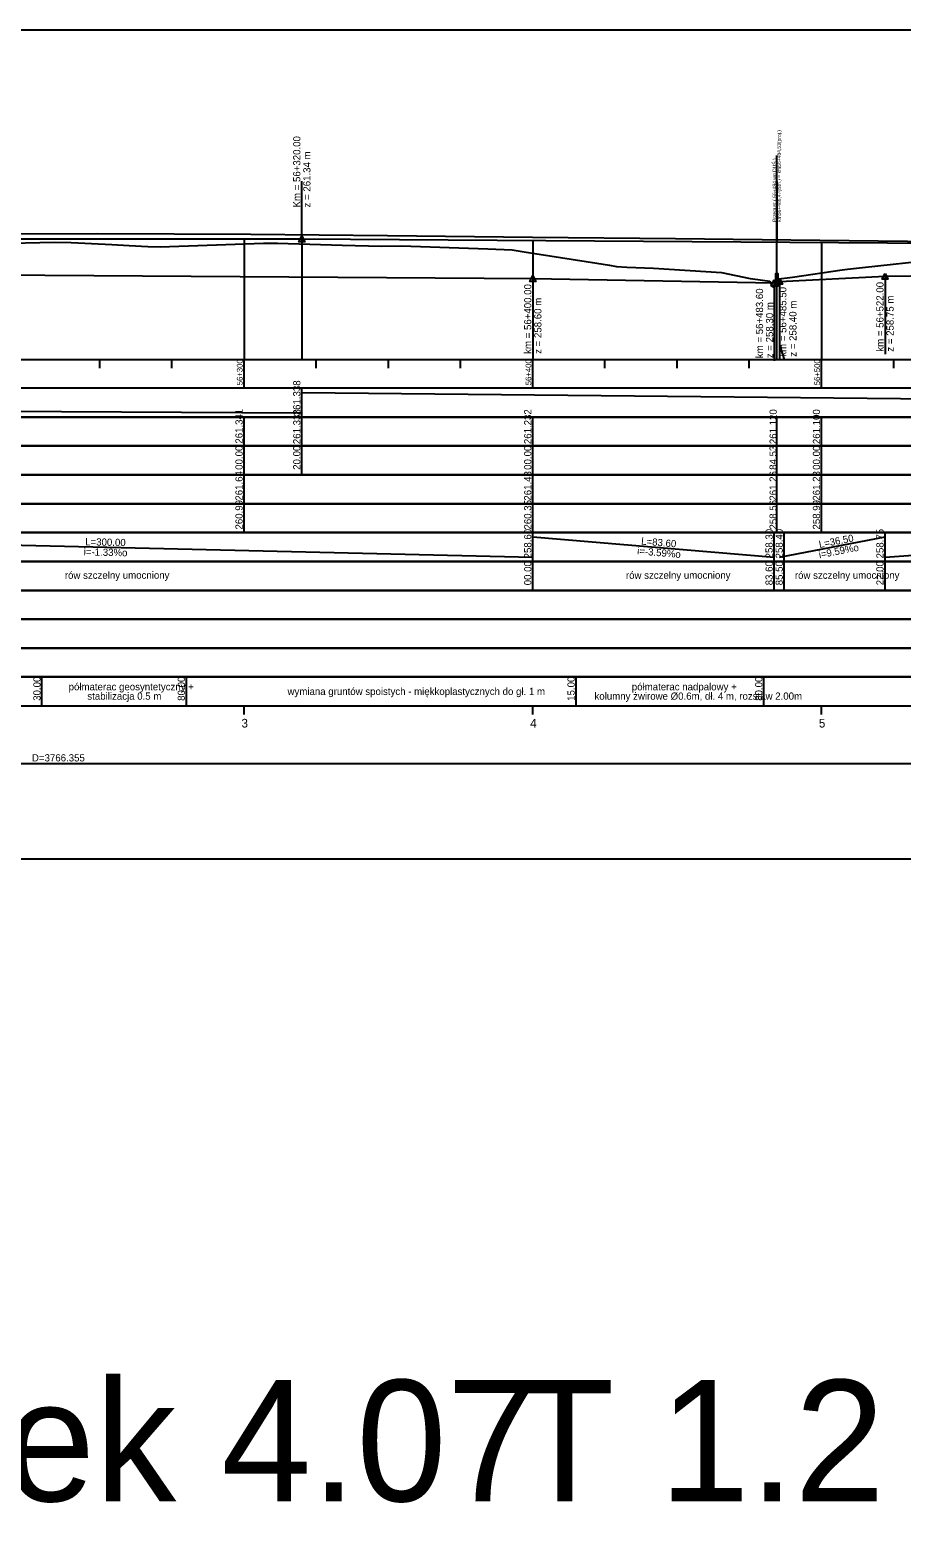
# Model space of a CAD drawing. Extents: x 6445630 to 6518227, y 5499240 to 5511716.
# Drawn here: x 6455457 to 6455759, y 5508183 to 5508705 of the extents above; entities that cross this region are included whole.
import ezdxf

# ---------------------------------------------------------------- set-up
doc = ezdxf.new("R2010")
doc.units = 0
for name, color, linetype in [('TOR_PROF-obiekty+opisy', 7, 'Continuous'), ('TOR_PROF-opisy pomocnicze', 7, 'Continuous'), ('TOR_PROF-rowy otwarte', 7, 'Continuous'), ('TOR_PROF-tabelka-geometria T1', 7, 'Continuous'), ('TOR_PROF-tabelka-kilometracja', 7, 'Continuous'), ('TOR_PROF-tabelka-odleglosci T1', 7, 'Continuous'), ('TOR_PROF-tabelka-pochylenia proj T1', 7, 'Continuous'), ('TOR_PROF-tabelka-rodzaj rowu T1', 7, 'Continuous'), ('TOR_PROF-tabelka-rowyT1', 7, 'Continuous'), ('TOR_PROF-tabelka-rurociagi T1', 7, 'Continuous'), ('TOR_PROF-tabelka-rzedne istn T1', 7, 'Continuous'), ('TOR_PROF-tabelka-rzedne proj T1', 7, 'Continuous'), ('TOR_PROF-tabelka-teren istniejacy T1', 7, 'Continuous'), ('TOR_PROF-tabelka-warstwa ochronna T1', 7, 'Continuous'), ('TOR_PROF-tor istniejacy T2', 7, 'Continuous'), ('TOR_PROF-tor projektowany', 7, 'Continuous'), ('TOR_PROF-uklad odniesienia', 7, 'Continuous'), ('TOR_PROF-warstwa ochronna', 7, 'Continuous'), ('TOR_RAMKI-dodatkowe3', 7, 'Continuous'), ('TOR_RAMKI-MASKA WYCIECIA', 7, 'Continuous')]:
    doc.layers.add(name, color=color, linetype=linetype)

msp = doc.modelspace()

# ---------------------------------------------------------------- linework, layer by layer
at = {"layer": 'TOR_PROF-obiekty+opisy'}
for p, q in [((6455715.74, 5508591.29), (6455715.74, 5508661.89)), ((6455715.74, 5508652.89), (6455715.74, 5508631.89))]:
    msp.add_line(p, q, dxfattribs=at)
for points in [[(6455716.2, 5508620.87), (6455715.28, 5508620.87), (6455715.28, 5508616.79), (6455716.2, 5508616.79)], [(6455716.12, 5508620.33), (6455715.37, 5508620.33), (6455715.37, 5508617.33), (6455716.12, 5508617.33)]]:
    msp.add_lwpolyline(points, close=True, dxfattribs=at)
for points in [[(6455716.2, 5508616.79), (6455716.2, 5508620.87), (6455715.28, 5508620.87), (6455715.28, 5508616.79), (6455716.2, 5508616.79)], [(6455716.12, 5508617.33), (6455715.37, 5508617.33), (6455715.37, 5508620.33), (6455716.12, 5508620.33), (6455716.12, 5508617.33)]]:
    msp.add_lwpolyline(points, dxfattribs=at)
at = {"layer": 'TOR_PROF-opisy pomocnicze'}
for p, q in [((6455551.21, 5508632.98), (6455551.21, 5508652.98)), ((6455551.21, 5508632.98), (6455551.21, 5508652.98)), ((6455631.21, 5508619.29), (6455631.21, 5508592.29)), ((6455714.81, 5508617.79), (6455714.81, 5508590.79)), ((6455716.71, 5508618.29), (6455716.71, 5508591.29)), ((6455753.21, 5508620.04), (6455753.21, 5508593.04))]:
    msp.add_line(p, q, dxfattribs=at)
for points in [[(6455551.21, 5508633.98), (6455552.21, 5508631.98), (6455550.21, 5508631.98)], [(6455551.21, 5508633.98), (6455552.21, 5508631.98), (6455550.21, 5508631.98)], [(6455631.21, 5508620.29), (6455632.21, 5508618.29), (6455630.21, 5508618.29)], [(6455714.81, 5508618.79), (6455715.81, 5508616.79), (6455713.81, 5508616.79)], [(6455716.71, 5508619.29), (6455717.71, 5508617.29), (6455715.71, 5508617.29)], [(6455753.21, 5508621.04), (6455754.21, 5508619.04), (6455752.21, 5508619.04)]]:
    msp.add_lwpolyline(points, close=True, dxfattribs=at)
at = {"layer": 'TOR_PROF-rowy otwarte'}
for p, q in [((6455331.21, 5508621.29), (6455631.21, 5508619.29)), ((6455631.21, 5508619.29), (6455714.81, 5508617.79)), ((6455716.71, 5508618.29), (6455753.21, 5508620.04)), ((6455753.21, 5508620.04), (6455851.21, 5508621.79))]:
    msp.add_line(p, q, dxfattribs=at)
msp.add_lwpolyline([(6455716.71, 5508618.29), (6455716.71, 5508596.29), (6455718.31, 5508591.29), (6455718.31, 5508591.29)], dxfattribs=at)
at = {"layer": 'TOR_PROF-tabelka-geometria T1'}
for points in [[(6452331.21, 5508451.29), (6453331.21, 5508451.29), (6453331.21, 5508448.62), (6453416.22, 5508448.62), (6453416.22, 5508451.29), (6453496.22, 5508451.29), (6453496.22, 5508453.96), (6453581.21, 5508453.96), (6453581.21, 5508451.29), (6457347.56, 5508451.29), (6457347.56, 5508448.62), (6457429.11, 5508448.62), (6457429.11, 5508451.29), (6457509.11, 5508451.29), (6457509.11, 5508453.96), (6457590.67, 5508453.96), (6457590.67, 5508451.29), (6459780.93, 5508451.29)], [(6452331.21, 5508451.29), (6462731.21, 5508451.29)]]:
    msp.add_lwpolyline(points, dxfattribs=at)
at = {"layer": 'TOR_PROF-tabelka-kilometracja'}
for points in [[(6455531.21, 5508468.29), (6455531.21, 5508471.29)], [(6455631.21, 5508468.29), (6455631.21, 5508471.29)], [(6455731.21, 5508468.29), (6455731.21, 5508471.29)]]:
    msp.add_lwpolyline(points, dxfattribs=at)
at = {"layer": 'TOR_PROF-tabelka-odleglosci T1'}
msp.add_lwpolyline([(6452331.21, 5508551.29), (6462731.21, 5508551.29), (6462731.21, 5508561.29), (6452331.21, 5508561.29)], close=True, dxfattribs=at)
for points in [[(6455531.21, 5508551.29), (6455531.21, 5508561.29)], [(6455551.21, 5508551.29), (6455551.21, 5508561.29)], [(6455631.21, 5508551.29), (6455631.21, 5508561.29)], [(6455715.74, 5508551.29), (6455715.74, 5508561.29)], [(6455731.21, 5508551.29), (6455731.21, 5508561.29)]]:
    msp.add_lwpolyline(points, dxfattribs=at)
at = {"layer": 'TOR_PROF-tabelka-pochylenia proj T1'}
msp.add_lwpolyline([(6452331.21, 5508571.29), (6462731.21, 5508571.29), (6462731.21, 5508581.29), (6452331.21, 5508581.29)], close=True, dxfattribs=at)
for points in [[(6455551.21, 5508571.29), (6455551.21, 5508581.29)], [(6454281.21, 5508579.79), (6455551.21, 5508572.79)], [(6455551.21, 5508579.79), (6456253.75, 5508572.79)]]:
    msp.add_lwpolyline(points, dxfattribs=at)
at = {"layer": 'TOR_PROF-tabelka-rodzaj rowu T1'}
for points in [[(6452331.21, 5508511.29), (6462731.21, 5508511.29), (6462731.21, 5508521.29), (6452331.21, 5508521.29)], [(6452331.21, 5508511.29), (6462731.21, 5508511.29), (6462731.21, 5508521.29), (6452331.21, 5508521.29)], [(6452331.21, 5508491.29), (6462731.21, 5508491.29), (6462731.21, 5508501.29), (6452331.21, 5508501.29)]]:
    msp.add_lwpolyline(points, close=True, dxfattribs=at)
for points in [[(6455631.21, 5508511.29), (6455631.21, 5508521.29)], [(6455714.81, 5508511.29), (6455714.81, 5508521.29)], [(6455718.31, 5508511.29), (6455718.31, 5508521.29)], [(6455753.21, 5508511.29), (6455753.21, 5508521.29)]]:
    msp.add_lwpolyline(points, dxfattribs=at)
at = {"layer": 'TOR_PROF-tabelka-rowyT1'}
msp.add_lwpolyline([(6452331.21, 5508521.29), (6462731.21, 5508521.29), (6462731.21, 5508531.29), (6452331.21, 5508531.29)], close=True, dxfattribs=at)
msp.add_lwpolyline([(6452331.21, 5508521.29), (6462731.21, 5508521.29), (6462731.21, 5508531.29), (6452331.21, 5508531.29)], close=True, dxfattribs=at)
msp.add_lwpolyline([(6452331.21, 5508521.29), (6462731.21, 5508521.29), (6462731.21, 5508531.29), (6452331.21, 5508531.29)], close=True, dxfattribs=at)
for points in [[(6455331.21, 5508529.79), (6455631.21, 5508522.79)], [(6455631.21, 5508521.29), (6455631.21, 5508531.29)], [(6455631.21, 5508529.79), (6455714.81, 5508522.79)], [(6455714.81, 5508521.29), (6455714.81, 5508531.29)], [(6455716.71, 5508522.79), (6455753.21, 5508529.79)], [(6455718.31, 5508521.29), (6455718.31, 5508531.29)], [(6455753.21, 5508521.29), (6455753.21, 5508531.29)], [(6455753.21, 5508522.79), (6455851.21, 5508529.79)]]:
    msp.add_lwpolyline(points, dxfattribs=at)
at = {"layer": 'TOR_PROF-tabelka-rurociagi T1'}
msp.add_lwpolyline([(6452331.21, 5508501.29), (6462731.21, 5508501.29), (6462731.21, 5508511.29), (6452331.21, 5508511.29)], close=True, dxfattribs=at)
at = {"layer": 'TOR_PROF-tabelka-rzedne istn T1'}
msp.add_lwpolyline([(6452331.21, 5508541.29), (6462731.21, 5508541.29), (6462731.21, 5508551.29), (6452331.21, 5508551.29)], close=True, dxfattribs=at)
for points in [[(6455531.21, 5508541.29), (6455531.21, 5508551.29)], [(6455631.21, 5508541.29), (6455631.21, 5508551.29)], [(6455715.74, 5508541.29), (6455715.74, 5508551.29)], [(6455731.21, 5508541.29), (6455731.21, 5508551.29)], [(6455531.21, 5508531.29), (6455531.21, 5508541.29)], [(6455531.21, 5508531.29), (6455531.21, 5508541.29)], [(6455531.21, 5508531.29), (6455531.21, 5508541.29)], [(6455531.21, 5508531.29), (6455531.21, 5508541.29)], [(6455631.21, 5508531.29), (6455631.21, 5508541.29)], [(6455631.21, 5508531.29), (6455631.21, 5508541.29)], [(6455631.21, 5508531.29), (6455631.21, 5508541.29)], [(6455631.21, 5508531.29), (6455631.21, 5508541.29)], [(6455715.74, 5508531.29), (6455715.74, 5508541.29)], [(6455731.21, 5508531.29), (6455731.21, 5508541.29)], [(6455731.21, 5508531.29), (6455731.21, 5508541.29)], [(6455731.21, 5508531.29), (6455731.21, 5508541.29)], [(6455731.21, 5508531.29), (6455731.21, 5508541.29)]]:
    msp.add_lwpolyline(points, dxfattribs=at)
at = {"layer": 'TOR_PROF-tabelka-rzedne proj T1'}
msp.add_lwpolyline([(6452331.21, 5508561.29), (6462731.21, 5508561.29), (6462731.21, 5508571.29), (6452331.21, 5508571.29)], close=True, dxfattribs=at)
for points in [[(6455531.21, 5508561.29), (6455531.21, 5508571.29)], [(6455551.21, 5508561.29), (6455551.21, 5508571.29)], [(6455631.21, 5508561.29), (6455631.21, 5508571.29)], [(6455715.74, 5508561.29), (6455715.74, 5508571.29)], [(6455731.21, 5508561.29), (6455731.21, 5508571.29)]]:
    msp.add_lwpolyline(points, dxfattribs=at)
at = {"layer": 'TOR_PROF-tabelka-teren istniejacy T1'}
msp.add_lwpolyline([(6452331.21, 5508531.29), (6462731.21, 5508531.29), (6462731.21, 5508541.29), (6452331.21, 5508541.29)], close=True, dxfattribs=at)
msp.add_lwpolyline([(6452331.21, 5508531.29), (6462731.21, 5508531.29), (6462731.21, 5508541.29), (6452331.21, 5508541.29)], close=True, dxfattribs=at)
msp.add_lwpolyline([(6452331.21, 5508531.29), (6462731.21, 5508531.29), (6462731.21, 5508541.29), (6452331.21, 5508541.29)], close=True, dxfattribs=at)
msp.add_lwpolyline([(6452331.21, 5508531.29), (6462731.21, 5508531.29), (6462731.21, 5508541.29), (6452331.21, 5508541.29)], close=True, dxfattribs=at)
at = {"layer": 'TOR_PROF-tabelka-warstwa ochronna T1'}
msp.add_lwpolyline([(6452331.21, 5508481.29), (6462731.21, 5508481.29), (6462731.21, 5508491.29), (6452331.21, 5508491.29)], close=True, dxfattribs=at)
at = {"layer": 'TOR_PROF-tor istniejacy T2'}
msp.add_lwpolyline([(6455781.22, 5508631.84), (6455730.64, 5508632.44), (6455680.65, 5508632.99), (6455631.1, 5508633.44), (6455580.84, 5508634.09), (6455533.6, 5508634.49), (6455480.41, 5508634.74), (6455431.02, 5508634.69), (6455379.72, 5508634.69), (6455329.04, 5508634.69), (6455279.58, 5508634.74), (6455230.6, 5508634.64), (6455180.37, 5508634.54)], dxfattribs=at)
at = {"layer": 'TOR_PROF-tor projektowany'}
for p, q in [((6454281.21, 5508633.98), (6455551.21, 5508632.98)), ((6454281.21, 5508633.98), (6455551.21, 5508632.98)), ((6455551.21, 5508632.98), (6456180.45, 5508628.82)), ((6455551.21, 5508632.98), (6456253.75, 5508628.33))]:
    msp.add_line(p, q, dxfattribs=at)
for points in [[(6455531.21, 5508633), (6455531.21, 5508596.29), (6455531.21, 5508591.29), (6455531.21, 5508591.29)], [(6455531.21, 5508633), (6455531.21, 5508596.29), (6455531.21, 5508591.29), (6455531.21, 5508591.29)], [(6455551.21, 5508632.98), (6455551.21, 5508596.29), (6455551.21, 5508591.29), (6455551.21, 5508591.29)], [(6455551.21, 5508632.98), (6455551.21, 5508596.29), (6455551.21, 5508591.29), (6455551.21, 5508591.29)], [(6455551.21, 5508632.98), (6455551.21, 5508596.29), (6455551.21, 5508591.29), (6455551.21, 5508591.29)], [(6455551.21, 5508632.98), (6455551.21, 5508596.29), (6455551.21, 5508591.29), (6455551.21, 5508591.29)], [(6455631.21, 5508632.45), (6455631.21, 5508596.29), (6455631.21, 5508591.29), (6455631.21, 5508591.29)], [(6455631.21, 5508632.45), (6455631.21, 5508596.29), (6455631.21, 5508591.29), (6455631.21, 5508591.29)], [(6455731.21, 5508631.79), (6455731.21, 5508596.29), (6455731.21, 5508591.29), (6455731.21, 5508591.29)], [(6455731.21, 5508631.79), (6455731.21, 5508596.29), (6455731.21, 5508591.29), (6455731.21, 5508591.29)]]:
    msp.add_lwpolyline(points, dxfattribs=at)
at = {"layer": 'TOR_PROF-uklad odniesienia'}
for p, q in [((6452331.21, 5508591.29), (6462731.21, 5508591.29)), ((6452331.21, 5508591.29), (6462731.21, 5508591.29)), ((6455481.21, 5508588.29), (6455481.21, 5508591.29)), ((6455481.21, 5508588.29), (6455481.21, 5508591.29)), ((6455506.21, 5508588.29), (6455506.21, 5508591.29)), ((6455506.21, 5508588.29), (6455506.21, 5508591.29)), ((6455531.21, 5508581.29), (6455531.21, 5508591.29)), ((6455531.21, 5508581.29), (6455531.21, 5508591.29)), ((6455556.21, 5508588.29), (6455556.21, 5508591.29)), ((6455556.21, 5508588.29), (6455556.21, 5508591.29)), ((6455581.21, 5508588.29), (6455581.21, 5508591.29)), ((6455581.21, 5508588.29), (6455581.21, 5508591.29)), ((6455606.21, 5508588.29), (6455606.21, 5508591.29)), ((6455606.21, 5508588.29), (6455606.21, 5508591.29)), ((6455631.21, 5508581.29), (6455631.21, 5508591.29)), ((6455631.21, 5508581.29), (6455631.21, 5508591.29)), ((6455656.21, 5508588.29), (6455656.21, 5508591.29)), ((6455656.21, 5508588.29), (6455656.21, 5508591.29)), ((6455681.21, 5508588.29), (6455681.21, 5508591.29)), ((6455681.21, 5508588.29), (6455681.21, 5508591.29)), ((6455706.21, 5508588.29), (6455706.21, 5508591.29)), ((6455706.21, 5508588.29), (6455706.21, 5508591.29)), ((6455731.21, 5508581.29), (6455731.21, 5508591.29)), ((6455731.21, 5508581.29), (6455731.21, 5508591.29)), ((6455756.21, 5508588.29), (6455756.21, 5508591.29)), ((6455756.21, 5508588.29), (6455756.21, 5508591.29))]:
    msp.add_line(p, q, dxfattribs=at)
at = {"layer": 'TOR_PROF-warstwa ochronna'}
msp.add_lwpolyline([(6452331.21, 5508471.29), (6462731.21, 5508471.29), (6462731.21, 5508481.29), (6452331.21, 5508481.29)], close=True, dxfattribs=at)
for points in [[(6455461.21, 5508471.29), (6455461.21, 5508481.29)], [(6455511.21, 5508471.29), (6455511.21, 5508481.29)], [(6455646.21, 5508471.29), (6455646.21, 5508481.29)], [(6455711.21, 5508471.29), (6455711.21, 5508481.29)]]:
    msp.add_lwpolyline(points, dxfattribs=at)
at = {"layer": 'TOR_RAMKI-dodatkowe3'}
for p, q in [((6455439.28, 5508631.3), (6455465.57, 5508631.92)), ((6455465.57, 5508631.92), (6455471.29, 5508631.8)), ((6455471.29, 5508631.8), (6455485.43, 5508631.04)), ((6455485.43, 5508631.04), (6455491.36, 5508630.74)), ((6455491.36, 5508630.74), (6455497.84, 5508630.4)), ((6455497.84, 5508630.4), (6455502.18, 5508630.24)), ((6455502.18, 5508630.24), (6455537.96, 5508631.47)), ((6455537.96, 5508631.47), (6455541.42, 5508631.48)), ((6455541.42, 5508631.48), (6455541.89, 5508631.48)), ((6455541.89, 5508631.48), (6455542.76, 5508631.48)), ((6455542.76, 5508631.48), (6455565.24, 5508630.84)), ((6455565.24, 5508630.84), (6455578.8, 5508630.54)), ((6455578.8, 5508630.54), (6455585.63, 5508630.63)), ((6455585.63, 5508630.63), (6455615.65, 5508629.52)), ((6455615.65, 5508629.52), (6455624.02, 5508629.19)), ((6455624.02, 5508629.19), (6455628.2, 5508628.49)), ((6455628.2, 5508628.49), (6455653.4, 5508624.56)), ((6455653.4, 5508624.56), (6455657.77, 5508623.86)), ((6455657.77, 5508623.86), (6455660.22, 5508623.44)), ((6455660.22, 5508623.44), (6455663.8, 5508623.25)), ((6455663.8, 5508623.25), (6455673.06, 5508622.86)), ((6455673.06, 5508622.86), (6455696.53, 5508621.42)), ((6455721.11, 5508619.79), (6455738.35, 5508622.29)), ((6455738.35, 5508622.29), (6455740.19, 5508622.55)), ((6455740.19, 5508622.55), (6455745.45, 5508623.12)), ((6455745.45, 5508623.12), (6455775.55, 5508626.44)), ((6455696.53, 5508621.42), (6455706.56, 5508619.34)), ((6455706.56, 5508619.34), (6455706.58, 5508619.33)), ((6455706.58, 5508619.33), (6455713.27, 5508618.34)), ((6455713.27, 5508618.34), (6455713.66, 5508617.47)), ((6455713.66, 5508617.47), (6455714.26, 5508616.4)), ((6455714.79, 5508616.49), (6455715.03, 5508617.9)), ((6455715.03, 5508617.9), (6455715.3, 5508619.01)), ((6455715.3, 5508619.01), (6455715.52, 5508619.07)), ((6455715.52, 5508619.07), (6455721.11, 5508619.79)), ((6455714.26, 5508616.4), (6455714.46, 5508616.44)), ((6455714.46, 5508616.44), (6455714.79, 5508616.49))]:
    msp.add_line(p, q, dxfattribs=at)
at = {"layer": 'TOR_RAMKI-MASKA WYCIECIA'}
msp.add_lwpolyline([(6454268.59, 5508418.29), (6456268.59, 5508418.29), (6456268.59, 5508705.29), (6454268.59, 5508705.29)], close=True, dxfattribs=at)

# ---------------------------------------------------------------- texts
at = {"layer": 'TOR_PROF-obiekty+opisy'}
for s, p in [(' km56+486,47(istn.) = km56+484,53(proj.) ', (6455717.13, 5508638.39)), (' Przepust ( 56+484 wg DUŚ )', (6455715.52, 5508638.39))]:
    msp.add_text(s, height=1.25, rotation=90, dxfattribs=at).set_placement(p)
at = {"layer": 'TOR_PROF-opisy pomocnicze'}
for s, p in [('Km = 56+320.00', (6455550.71, 5508643.88)), ('Km = 56+320.00', (6455550.71, 5508643.88)), ('z = 261.34 m', (6455554.21, 5508643.88)), ('z = 261.34 m', (6455554.21, 5508643.88)), ('km = 56+400.00', (6455630.71, 5508593.19)), ('km = 56+522.00', (6455752.71, 5508593.94)), ('z = 258.60 m', (6455634.21, 5508593.19)), ('km = 56+483.60', (6455710.98, 5508591.69)), ('km = 56+485.50', (6455719.06, 5508592.19)), ('z = 258.75 m', (6455756.21, 5508593.94)), ('z = 258.30 m', (6455714.48, 5508591.69)), ('z = 258.40 m', (6455722.56, 5508592.19))]:
    msp.add_text(s, height=2.5, rotation=90, dxfattribs=at).set_placement(p)
at = {"layer": 'TOR_PROF-tabelka-geometria T1'}
msp.add_text('D=3766.355', height=2.5, dxfattribs=at).set_placement((6455457.74, 5508452.04))
at = {"layer": 'TOR_PROF-tabelka-kilometracja'}
for s, p in [('3', (6455530.32, 5508463.79)), ('4', (6455630.32, 5508463.79)), ('5', (6455730.31, 5508463.79))]:
    msp.add_text(s, height=3, dxfattribs=at).set_placement(p)
at = {"layer": 'TOR_PROF-tabelka-odleglosci T1'}
for s, p in [('00.00', (6455530.71, 5508553.03)), ('20.00', (6455550.71, 5508553.03)), ('00.00', (6455630.71, 5508553.03)), ('84.53', (6455715.71, 5508553.03)), ('00.00', (6455730.71, 5508553.03))]:
    msp.add_text(s, height=2.5, rotation=90, dxfattribs=at).set_placement(p)
at = {"layer": 'TOR_PROF-tabelka-pochylenia proj T1'}
msp.add_text('261.338', height=2.5, rotation=90, dxfattribs=at).set_placement((6455550.71, 5508571.92))
at = {"layer": 'TOR_PROF-tabelka-rodzaj rowu T1'}
for s, p in [('00.00', (6455630.71, 5508513.04)), ('83.60', (6455714.31, 5508513.04)), ('85.50', (6455717.81, 5508513.04)), ('22.00', (6455752.71, 5508513.04))]:
    msp.add_text(s, height=2.5, rotation=90, dxfattribs=at).set_placement(p)
at = {"layer": 'TOR_PROF-tabelka-rowyT1'}
for s, rotation, p in [('L=300.00', 358.6633, (6455476.15, 5508526.91)), ('258.60', 90, (6455630.71, 5508522.36)), ('L=83.60', 355.2137, (6455668.67, 5508527.15)), ('258.30', 90, (6455714.31, 5508522.36)), ('258.40', 90, (6455717.81, 5508522.36)), ('L=36.50', 10.8564, (6455730.55, 5508525.95)), ('258.75', 90, (6455752.71, 5508522.35)), ('i=-1.33%o', 358.6633, (6455475.64, 5508523.42)), ('i=-3.59%o', 355.2137, (6455667.28, 5508523.76)), ('i=9.59%o', 10.8564, (6455730.52, 5508522.38)), ('rów szczelny umocniony', 0.087, (6455469.13, 5508515.27)), ('rów szczelny umocniony', 0.087, (6455663.47, 5508515.27)), ('rów szczelny umocniony', 0.087, (6455721.99, 5508515.27))]:
    msp.add_text(s, height=2.5, rotation=rotation, dxfattribs=at).set_placement(p)
at = {"layer": 'TOR_PROF-tabelka-rzedne istn T1'}
for s, p in [('261.64', (6455530.71, 5508542.36)), ('261.43', (6455630.71, 5508542.35)), ('261.26', (6455715.71, 5508542.35)), ('261.23', (6455730.71, 5508542.35)), ('260.99', (6455530.71, 5508532.36)), ('260.35', (6455630.71, 5508532.35)), ('258.56', (6455715.71, 5508532.35)), ('258.99', (6455730.71, 5508532.36))]:
    msp.add_text(s, height=2.5, rotation=90, dxfattribs=at).set_placement(p)
at = {"layer": 'TOR_PROF-tabelka-rzedne proj T1'}
for s, p in [('261.341', (6455530.71, 5508562.09)), ('261.338', (6455550.71, 5508561.92)), ('261.232', (6455630.71, 5508561.93)), ('261.120', (6455715.71, 5508561.93)), ('261.100', (6455730.71, 5508561.93))]:
    msp.add_text(s, height=2.5, rotation=90, dxfattribs=at).set_placement(p)
at = {"layer": 'TOR_PROF-uklad odniesienia'}
for s, p in [('56+300', (6455530.71, 5508582.31)), ('56+300', (6455530.71, 5508582.31)), ('56+400', (6455630.71, 5508582.31)), ('56+400', (6455630.71, 5508582.31)), ('56+500', (6455730.71, 5508582.31)), ('56+500', (6455730.71, 5508582.31))]:
    msp.add_text(s, height=2, rotation=90, dxfattribs=at).set_placement(p)
for s, p in [('Rysunek 4.07', (6455289.16, 5508195.84)), ('T 1.2', (6455625.16, 5508195.84))]:
    msp.add_text(s, height=42, dxfattribs=at).set_placement(p)
at = {"layer": 'TOR_PROF-warstwa ochronna'}
for s, rotation, p in [('30.00', 90, (6455460.71, 5508473.04)), ('80.00', 90, (6455510.71, 5508473.04)), ('15.00', 90, (6455645.71, 5508473.04)), ('80.00', 90, (6455710.71, 5508473.04)), ('półmaterac geosyntetyczny +', 360, (6455470.44, 5508476.66)), ('stabilizacja 0.5 m', 360, (6455476.92, 5508473.42)), ('wymiana gruntów spoistych - miękkoplastycznych do gł. 1 m', 360, (6455546.26, 5508475.04)), ('kolumny żwirowe Ø0.6m, dł. 4 m, rozstaw 2.00m', 360, (6455652.58, 5508473.42)), ('półmaterac nadpalowy +', 360, (6455665.51, 5508476.66))]:
    msp.add_text(s, height=2.5, rotation=rotation, dxfattribs=at).set_placement(p)

doc.saveas('drawing.dxf')
